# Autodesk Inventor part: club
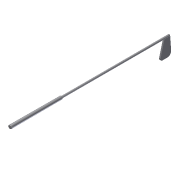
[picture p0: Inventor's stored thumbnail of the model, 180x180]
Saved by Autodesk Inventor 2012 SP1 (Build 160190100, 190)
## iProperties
Created: 2014-08
Part Number: club
Material: Default
Document SubType Name: Modeling
Designer: Bruno
Density: 1 g/cm^3
Author: Bruno
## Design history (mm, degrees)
sketch "Esquisse1"
  geometry: L1 (0, 0)-(0, 830); L2 (0, 830)-(5, 830); L3 (5, 830)-(5, 268.843); L4 (5, 268.843)-(5.994, 268.843); L5 (7.994, 266.851)-(8.971, 2.007); L6 (6.971, 0)-(0, 0); A1 r 2 centre (5.994, 266.843) between (7.994, 266.851) and (5.994, 268.843); A2 r 2 centre (6.971, 2) between (6.971, 0) and (8.971, 2.007)
  constraints: 12 end point, 4 point on circle, 4 tangent, 3 perpendicular, 2 centre point, 1 equal radius, 1 parallel, 1 vertical
  dimensions: "d0" = 830 distance of L1.start L1.end; "d1" = 5 distance of L1.end L2.end; "d2" = 2 radius of A1
revolve "Révolution1" sketch "Esquisse1" stored, may be unused: angle "d3" = 90 deg
sketch "Esquisse2"
  geometry: L1 (829.241, -1.346)-(834.131, -69.923); L2 (814.181, -91.346)-(788.616, -91.346); L3 (778.943, -78.811)-(799.241, -1.346); L4 (799.241, -1.346)-(829.241, -1.346); A1 r 20 centre (814.181, -71.346) between (814.181, -91.346) and (834.131, -69.923); A2 r 5 centre (782.137, -86.346) between (777.3, -85.079) and (782.137, -91.346); A3 r 10 centre (788.616, -81.346) between (778.943, -78.811) and (788.616, -91.346); 3 further points
  constraints: 8 end point, 6 point on circle, 6 point on line, 6 tangent, 3 centre point, 1 horizontal, 1 parallel
  dimensions: "d4" = 90 distance between parallel lines of L2 L4; "d5" = 60 distance of point (835.658, -91.346) point (775.658, -91.346); "d6" = 30 distance of L3.end L1.start; "d7" = 20 radius of A1; "d8" = 5 radius of A2; "d9" = 10 radius of A3
extrude "Extrusion1" join sketch "Esquisse2" distance "d10" = 5; taper "d12" = 0 deg; dims "d11" = 2.5, "d13" = 0
fillet "Congé1" dims "d14" = 2
node "Solide1"
